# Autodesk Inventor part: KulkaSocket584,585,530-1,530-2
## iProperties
Created: 2006-08
Part Number: KulkaSocket584,585,530-1,530-2
Document SubType Name: Sheet Metal
Designer: Administrator
Author: Administrator
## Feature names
1. Plate1
2. Cut1
